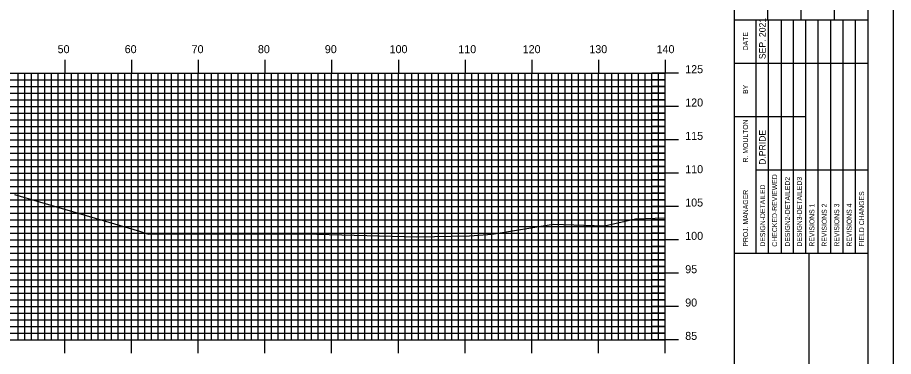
# Model space of a CAD drawing. Extents: x 1684405 to 1684749, y 461260 to 461480.
# Drawn here: x 1684614.1 to 1684745.4, y 461340.6 to 461391.4 of the extents above; entities that cross this region are included whole.
import ezdxf

# ---------------------------------------------------------------- set-up
doc = ezdxf.new("R2010")
doc.units = 0
for name, color, linetype in [('BORDER', 7, 'Continuous'), ('H_V ANNOTATION', 7, 'Continuous'), ('MAJOR', 7, 'Continuous'), ('MINOR', 7, 'Continuous'), ('PLOT BOUNDARY', 7, 'Continuous'), ('S_Roadway_Centerline', 7, 'Continuous')]:
    doc.layers.add(name, color=color, linetype=linetype)

msp = doc.modelspace()

# ---------------------------------------------------------------- linework, layer by layer
at = {"layer": 'BORDER'}
for p, q in [((1684721.6, 461266.07), (1684721.6, 461476.07)), ((1684726.6, 461391.08), (1684726.6, 461408.37)), ((1684731.6, 461391.08), (1684731.6, 461408.37)), ((1684736.6, 461391.08), (1684736.6, 461408.37)), ((1684721.6, 461391.08), (1684741.6, 461391.08)), ((1684721.6, 461356.08), (1684741.6, 461356.08)), ((1684732.79, 461286.08), (1684732.79, 461356.08))]:
    msp.add_line(p, q, dxfattribs=at)
msp.add_lwpolyline([(1684421.6, 461266.07), (1684741.6, 461266.07), (1684741.6, 461476.07), (1684421.6, 461476.07)], close=True, dxfattribs=at)
for points in [[(1684724.83, 461384.58), (1684724.83, 461391.08)], [(1684726.7, 461356.08), (1684726.7, 461391.08)], [(1684728.56, 461391.08), (1684728.56, 461356.08)], [(1684730.42, 461356.08), (1684730.42, 461391.08)], [(1684732.29, 461356.08), (1684732.29, 461391.08)], [(1684734.15, 461356.08), (1684734.15, 461391.08)], [(1684736.01, 461356.08), (1684736.01, 461391.08)], [(1684737.88, 461356.08), (1684737.88, 461391.08)], [(1684739.74, 461356.08), (1684739.74, 461391.08)], [(1684724.83, 461356.08), (1684724.83, 461389.67)], [(1684721.6, 461384.58), (1684741.6, 461384.58)], [(1684721.6, 461376.58), (1684724.83, 461376.58)], [(1684724.83, 461376.58), (1684732.29, 461376.58)], [(1684724.83, 461368.58), (1684741.6, 461368.58)]]:
    msp.add_lwpolyline(points, dxfattribs=at)
at = {"layer": 'MAJOR'}
for p, q in [((1684621.2, 461385.08), (1684621.2, 461383.07)), ((1684631.2, 461385.08), (1684631.2, 461383.07)), ((1684641.2, 461385.08), (1684641.2, 461383.07)), ((1684651.2, 461385.08), (1684651.2, 461383.07)), ((1684661.2, 461385.08), (1684661.2, 461383.07)), ((1684671.2, 461385.08), (1684671.2, 461383.07)), ((1684681.2, 461385.08), (1684681.2, 461383.07)), ((1684691.2, 461385.08), (1684691.2, 461383.07)), ((1684701.2, 461385.08), (1684701.2, 461383.07)), ((1684711.2, 461385.08), (1684711.2, 461383.07)), ((1684431.2, 461383.07), (1684711.2, 461383.07)), ((1684431.2, 461383.07), (1684711.2, 461383.07)), ((1684621.2, 461343.07), (1684621.2, 461383.07)), ((1684631.2, 461343.07), (1684631.2, 461383.07)), ((1684641.2, 461343.07), (1684641.2, 461383.07)), ((1684651.2, 461343.07), (1684651.2, 461383.07)), ((1684661.2, 461343.07), (1684661.2, 461383.07)), ((1684671.2, 461343.07), (1684671.2, 461383.07)), ((1684681.2, 461343.07), (1684681.2, 461383.07)), ((1684691.2, 461343.07), (1684691.2, 461383.07)), ((1684701.2, 461343.07), (1684701.2, 461383.07)), ((1684713.21, 461383.07), (1684709.2, 461383.07)), ((1684711.2, 461343.07), (1684711.2, 461383.07)), ((1684711.2, 461343.07), (1684711.2, 461383.07)), ((1684431.2, 461378.07), (1684711.2, 461378.07)), ((1684713.21, 461378.07), (1684709.2, 461378.07)), ((1684431.2, 461373.07), (1684711.2, 461373.07)), ((1684713.21, 461373.07), (1684709.2, 461373.07)), ((1684431.2, 461368.07), (1684711.2, 461368.07)), ((1684713.21, 461368.07), (1684709.2, 461368.07)), ((1684431.2, 461363.07), (1684711.2, 461363.07)), ((1684713.21, 461363.07), (1684709.2, 461363.07)), ((1684431.2, 461358.07), (1684711.2, 461358.07)), ((1684713.21, 461358.07), (1684709.2, 461358.07)), ((1684431.2, 461353.07), (1684711.2, 461353.07)), ((1684713.21, 461353.07), (1684709.2, 461353.07)), ((1684431.2, 461348.07), (1684711.2, 461348.07)), ((1684713.21, 461348.07), (1684709.2, 461348.07)), ((1684431.2, 461343.07), (1684711.2, 461343.07)), ((1684431.2, 461343.07), (1684711.2, 461343.07)), ((1684621.2, 461341.07), (1684621.2, 461343.07)), ((1684631.2, 461341.07), (1684631.2, 461343.07)), ((1684641.2, 461341.07), (1684641.2, 461343.07)), ((1684651.2, 461341.07), (1684651.2, 461343.07)), ((1684661.2, 461341.07), (1684661.2, 461343.07)), ((1684671.2, 461341.07), (1684671.2, 461343.07)), ((1684681.2, 461341.07), (1684681.2, 461343.07)), ((1684691.2, 461341.07), (1684691.2, 461343.07)), ((1684701.2, 461341.07), (1684701.2, 461343.07)), ((1684713.21, 461343.07), (1684709.2, 461343.07)), ((1684711.2, 461341.07), (1684711.2, 461343.07))]:
    msp.add_line(p, q, dxfattribs=at)
at = {"layer": 'MINOR'}
for p, q in [((1684614.2, 461343.07), (1684614.2, 461383.07)), ((1684615.2, 461343.07), (1684615.2, 461383.07)), ((1684616.2, 461343.07), (1684616.2, 461383.07)), ((1684617.2, 461343.07), (1684617.2, 461383.07)), ((1684618.2, 461343.07), (1684618.2, 461383.07)), ((1684619.2, 461343.07), (1684619.2, 461383.07)), ((1684620.2, 461343.07), (1684620.2, 461383.07)), ((1684622.2, 461343.07), (1684622.2, 461383.07)), ((1684623.2, 461343.07), (1684623.2, 461383.07)), ((1684624.2, 461343.07), (1684624.2, 461383.07)), ((1684625.2, 461343.07), (1684625.2, 461383.07)), ((1684626.2, 461343.07), (1684626.2, 461383.07)), ((1684627.2, 461343.07), (1684627.2, 461383.07)), ((1684628.2, 461343.07), (1684628.2, 461383.07)), ((1684629.2, 461343.07), (1684629.2, 461383.07)), ((1684630.2, 461343.07), (1684630.2, 461383.07)), ((1684632.2, 461343.07), (1684632.2, 461383.07)), ((1684633.2, 461343.07), (1684633.2, 461383.07)), ((1684634.2, 461343.07), (1684634.2, 461383.07)), ((1684635.2, 461343.07), (1684635.2, 461383.07)), ((1684636.2, 461343.07), (1684636.2, 461383.07)), ((1684637.2, 461343.07), (1684637.2, 461383.07)), ((1684638.2, 461343.07), (1684638.2, 461383.07)), ((1684639.2, 461343.07), (1684639.2, 461383.07)), ((1684640.2, 461343.07), (1684640.2, 461383.07)), ((1684642.2, 461343.07), (1684642.2, 461383.07)), ((1684643.2, 461343.07), (1684643.2, 461383.07)), ((1684644.2, 461343.07), (1684644.2, 461383.07)), ((1684645.2, 461343.07), (1684645.2, 461383.07)), ((1684646.2, 461343.07), (1684646.2, 461383.07)), ((1684647.2, 461343.07), (1684647.2, 461383.07)), ((1684648.2, 461343.07), (1684648.2, 461383.07)), ((1684649.2, 461343.07), (1684649.2, 461383.07)), ((1684650.2, 461343.07), (1684650.2, 461383.07)), ((1684652.2, 461343.07), (1684652.2, 461383.07)), ((1684653.2, 461343.07), (1684653.2, 461383.07)), ((1684654.2, 461343.07), (1684654.2, 461383.07)), ((1684655.2, 461343.07), (1684655.2, 461383.07)), ((1684656.2, 461343.07), (1684656.2, 461383.07)), ((1684657.2, 461343.07), (1684657.2, 461383.07)), ((1684658.2, 461343.07), (1684658.2, 461383.07)), ((1684659.2, 461343.07), (1684659.2, 461383.07)), ((1684660.2, 461343.07), (1684660.2, 461383.07)), ((1684662.2, 461343.07), (1684662.2, 461383.07)), ((1684663.2, 461343.07), (1684663.2, 461383.07)), ((1684664.2, 461343.07), (1684664.2, 461383.07)), ((1684665.2, 461343.07), (1684665.2, 461383.07)), ((1684666.2, 461343.07), (1684666.2, 461383.07)), ((1684667.2, 461343.07), (1684667.2, 461383.07)), ((1684668.2, 461343.07), (1684668.2, 461383.07)), ((1684669.2, 461343.07), (1684669.2, 461383.07)), ((1684670.2, 461343.07), (1684670.2, 461383.07)), ((1684672.2, 461343.07), (1684672.2, 461383.07)), ((1684673.2, 461343.07), (1684673.2, 461383.07)), ((1684674.2, 461343.07), (1684674.2, 461383.07)), ((1684675.2, 461343.07), (1684675.2, 461383.07)), ((1684676.2, 461343.07), (1684676.2, 461383.07)), ((1684677.2, 461343.07), (1684677.2, 461383.07)), ((1684678.2, 461343.07), (1684678.2, 461383.07)), ((1684679.2, 461343.07), (1684679.2, 461383.07)), ((1684680.2, 461343.07), (1684680.2, 461383.07)), ((1684682.2, 461343.07), (1684682.2, 461383.07)), ((1684683.2, 461343.07), (1684683.2, 461383.07)), ((1684684.2, 461343.07), (1684684.2, 461383.07)), ((1684685.2, 461343.07), (1684685.2, 461383.07)), ((1684686.2, 461343.07), (1684686.2, 461383.07)), ((1684687.2, 461343.07), (1684687.2, 461383.07)), ((1684688.2, 461343.07), (1684688.2, 461383.07)), ((1684689.2, 461343.07), (1684689.2, 461383.07)), ((1684690.2, 461343.07), (1684690.2, 461383.07)), ((1684692.2, 461343.07), (1684692.2, 461383.07)), ((1684693.2, 461343.07), (1684693.2, 461383.07)), ((1684694.2, 461343.07), (1684694.2, 461383.07)), ((1684695.2, 461343.07), (1684695.2, 461383.07)), ((1684696.2, 461343.07), (1684696.2, 461383.07)), ((1684697.2, 461343.07), (1684697.2, 461383.07)), ((1684698.2, 461343.07), (1684698.2, 461383.07)), ((1684699.2, 461343.07), (1684699.2, 461383.07)), ((1684700.2, 461343.07), (1684700.2, 461383.07)), ((1684702.2, 461343.07), (1684702.2, 461383.07)), ((1684703.2, 461343.07), (1684703.2, 461383.07)), ((1684704.2, 461343.07), (1684704.2, 461383.07)), ((1684705.2, 461343.07), (1684705.2, 461383.07)), ((1684706.2, 461343.07), (1684706.2, 461383.07)), ((1684707.2, 461343.07), (1684707.2, 461383.07)), ((1684708.2, 461343.07), (1684708.2, 461383.07)), ((1684709.2, 461343.07), (1684709.2, 461383.07)), ((1684710.2, 461343.07), (1684710.2, 461383.07)), ((1684431.2, 461382.07), (1684711.2, 461382.07)), ((1684431.2, 461381.07), (1684711.2, 461381.07)), ((1684711.2, 461382.07), (1684709.2, 461382.07)), ((1684711.2, 461381.07), (1684709.2, 461381.07)), ((1684431.2, 461380.07), (1684711.2, 461380.07)), ((1684711.2, 461380.07), (1684709.2, 461380.07)), ((1684431.2, 461379.07), (1684711.2, 461379.07)), ((1684711.2, 461379.07), (1684709.2, 461379.07)), ((1684431.2, 461377.07), (1684711.2, 461377.07)), ((1684711.2, 461377.07), (1684709.2, 461377.07)), ((1684431.2, 461376.07), (1684711.2, 461376.07)), ((1684711.2, 461376.07), (1684709.2, 461376.07)), ((1684431.2, 461375.07), (1684711.2, 461375.07)), ((1684711.2, 461375.07), (1684709.2, 461375.07)), ((1684431.2, 461374.07), (1684711.2, 461374.07)), ((1684711.2, 461374.07), (1684709.2, 461374.07)), ((1684431.2, 461372.07), (1684711.2, 461372.07)), ((1684711.2, 461372.07), (1684709.2, 461372.07)), ((1684431.2, 461371.07), (1684711.2, 461371.07)), ((1684711.2, 461371.07), (1684709.2, 461371.07)), ((1684431.2, 461370.07), (1684711.2, 461370.07)), ((1684711.2, 461370.07), (1684709.2, 461370.07)), ((1684431.2, 461369.07), (1684711.2, 461369.07)), ((1684711.2, 461369.07), (1684709.2, 461369.07)), ((1684431.2, 461367.07), (1684711.2, 461367.07)), ((1684711.2, 461367.07), (1684709.2, 461367.07)), ((1684431.2, 461366.07), (1684711.2, 461366.07)), ((1684711.2, 461366.07), (1684709.2, 461366.07)), ((1684431.2, 461365.07), (1684711.2, 461365.07)), ((1684431.2, 461364.07), (1684711.2, 461364.07)), ((1684711.2, 461365.07), (1684709.2, 461365.07)), ((1684711.2, 461364.07), (1684709.2, 461364.07)), ((1684431.2, 461362.07), (1684711.2, 461362.07)), ((1684711.2, 461362.07), (1684709.2, 461362.07)), ((1684431.2, 461361.07), (1684711.2, 461361.07)), ((1684431.2, 461360.07), (1684711.2, 461360.07)), ((1684711.2, 461361.07), (1684709.2, 461361.07)), ((1684711.2, 461360.07), (1684709.2, 461360.07)), ((1684431.2, 461359.07), (1684711.2, 461359.07)), ((1684711.2, 461359.07), (1684709.2, 461359.07)), ((1684431.2, 461357.07), (1684711.2, 461357.07)), ((1684431.2, 461356.07), (1684711.2, 461356.07)), ((1684711.2, 461357.07), (1684709.2, 461357.07)), ((1684711.2, 461356.07), (1684709.2, 461356.07)), ((1684431.2, 461355.07), (1684711.2, 461355.07)), ((1684711.2, 461355.07), (1684709.2, 461355.07)), ((1684431.2, 461354.07), (1684711.2, 461354.07)), ((1684711.2, 461354.07), (1684709.2, 461354.07)), ((1684431.2, 461352.07), (1684711.2, 461352.07)), ((1684711.2, 461352.07), (1684709.2, 461352.07)), ((1684431.2, 461351.07), (1684711.2, 461351.07)), ((1684711.2, 461351.07), (1684709.2, 461351.07)), ((1684431.2, 461350.07), (1684711.2, 461350.07)), ((1684711.2, 461350.07), (1684709.2, 461350.07)), ((1684431.2, 461349.07), (1684711.2, 461349.07)), ((1684711.2, 461349.07), (1684709.2, 461349.07)), ((1684431.2, 461347.07), (1684711.2, 461347.07)), ((1684711.2, 461347.07), (1684709.2, 461347.07)), ((1684431.2, 461346.07), (1684711.2, 461346.07)), ((1684711.2, 461346.07), (1684709.2, 461346.07)), ((1684431.2, 461345.07), (1684711.2, 461345.07)), ((1684711.2, 461345.07), (1684709.2, 461345.07)), ((1684431.2, 461344.07), (1684711.2, 461344.07)), ((1684711.2, 461344.07), (1684709.2, 461344.07))]:
    msp.add_line(p, q, dxfattribs=at)
at = {"layer": 'PLOT BOUNDARY'}
msp.add_lwpolyline([(1684405.42, 461259.95), (1684745.42, 461259.95), (1684745.42, 461479.95), (1684405.42, 461479.95)], close=True, dxfattribs=at)
at = {"layer": 'S_Roadway_Centerline'}
msp.add_lwpolyline([(1684613.66, 461364.89), (1684632.38, 461359.36), (1684633.41, 461359), (1684633.75, 461358.94), (1684634.84, 461358.96), (1684657.1, 461358.97), (1684673.95, 461358.51), (1684681.85, 461358.66), (1684685.24, 461358.94), (1684694.43, 461360.4), (1684702.09, 461360.17), (1684706.74, 461361.23), (1684711.2, 461361.38)], dxfattribs=at)

# ---------------------------------------------------------------- texts
at = {"layer": 'BORDER'}
for s, height, p in [('SEP. 2021', 0.969, (1684726.25, 461385.17)), ('DATE', 0.743, (1684723.61, 461386.49)), ('BY', 0.743, (1684723.61, 461379.95)), ('R. MOULTON', 0.745, (1684723.61, 461369.68)), ('D.PRIDE', 0.969, (1684726.25, 461369.32)), ('CHECKED-REVIEWED', 0.7455, (1684727.97, 461357.05)), ('DESIGN2-DETAILED2', 0.7455, (1684729.9, 461357.05)), ('DESIGN3-DETAILED3', 0.7455, (1684731.69, 461357.05)), ('PROJ. MANAGER', 0.7455, (1684723.61, 461357.05)), ('DESIGN-DETAILED', 0.7455, (1684726.18, 461357.05)), ('FIELD CHANGES', 0.7455, (1684741.01, 461357.05)), ('REVISIONS 1', 0.7455, (1684733.56, 461357.05)), ('REVISIONS 2', 0.7455, (1684735.42, 461357.05)), ('REVISIONS 3', 0.7455, (1684737.28, 461357.05)), ('REVISIONS 4', 0.7455, (1684739.15, 461357.05))]:
    msp.add_text(s, height=height, rotation=90, dxfattribs=at).set_placement(p)
at = {"layer": 'H_V ANNOTATION'}
for s, p in [('50', (1684620.13, 461386.07)), ('60', (1684630.18, 461386.07)), ('70', (1684640.21, 461386.07)), ('80', (1684650.15, 461386.07)), ('90', (1684660.18, 461386.07)), ('100', (1684669.89, 461386.07)), ('110', (1684680.19, 461386.07)), ('120', (1684689.84, 461386.07)), ('130', (1684699.83, 461386.07)), ('140', (1684709.91, 461386.07)), ('125', (1684714.2, 461383.07)), ('120', (1684714.2, 461378.07)), ('115', (1684714.2, 461373.07)), ('110', (1684714.2, 461368.07)), ('105', (1684714.2, 461363.07)), ('100', (1684714.2, 461358.07)), ('95', (1684714.2, 461353.07)), ('90', (1684714.2, 461348.07)), ('85', (1684714.2, 461343.07))]:
    msp.add_text(s, height=1.2, dxfattribs=at).set_placement(p)

doc.saveas('drawing.dxf')
